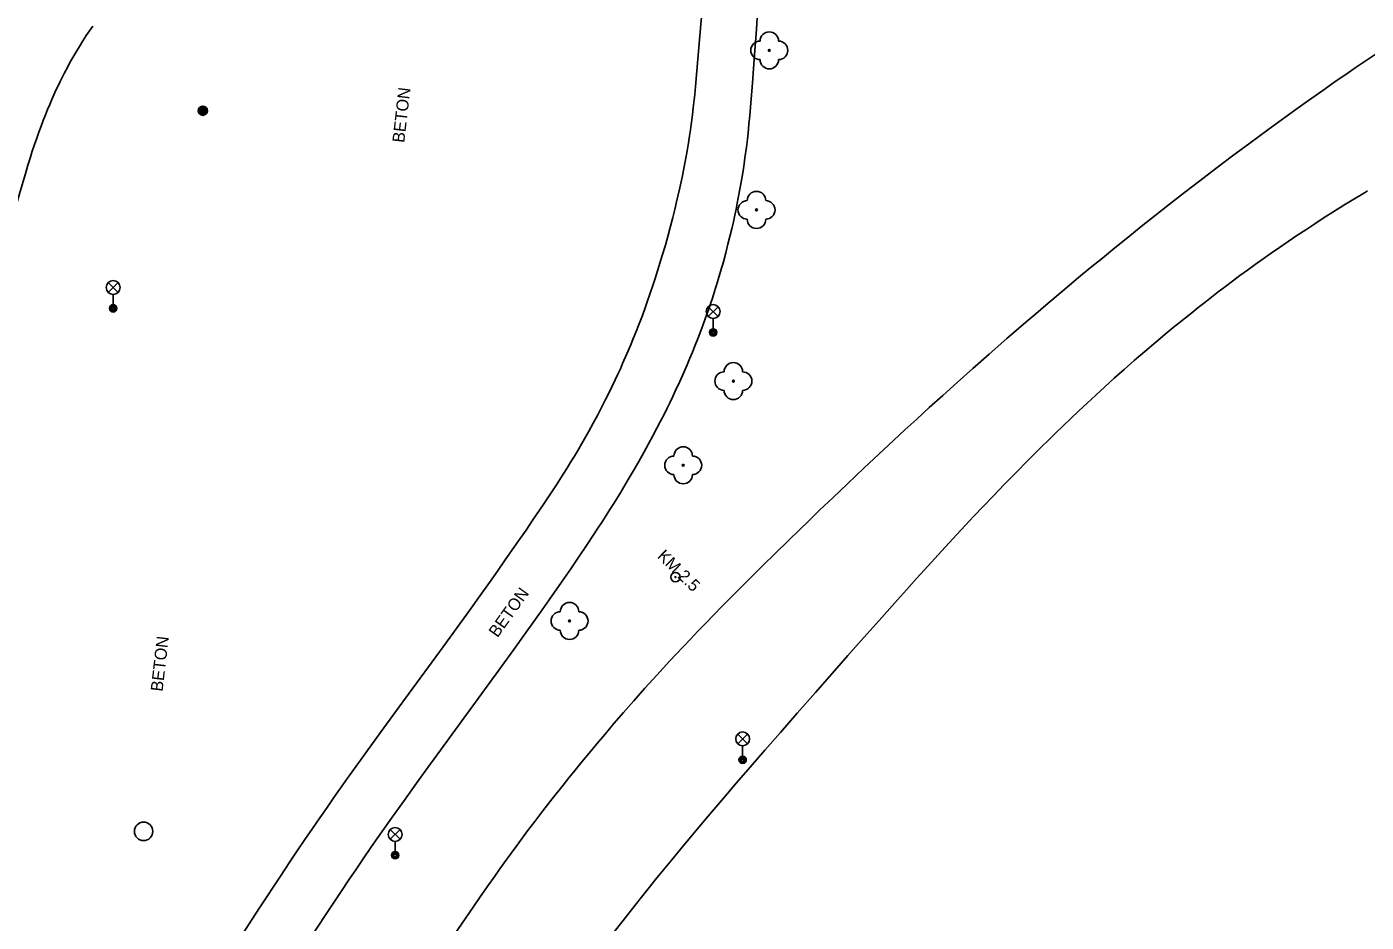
# Model space of a CAD drawing. Extents: x -541281 to -539153, y -1183881 to -1182141.
# Drawn here: x -539853.2 to -539780.8, y -1183251.4 to -1183203.1 of the extents above; entities that cross this region are included whole.
import ezdxf

# ---------------------------------------------------------------- set-up
doc = ezdxf.new("R2010")
doc.units = 0
for name, color, linetype in [('Vrstva 10', 7, 'Continuous'), ('Vrstva 11', 7, 'Continuous'), ('Vrstva 13', 7, 'Continuous'), ('Vrstva 22', 7, 'Continuous'), ('Vrstva 25', 7, 'Continuous'), ('Vrstva 27', 7, 'Continuous'), ('Vrstva 33', 7, 'Continuous'), ('Vrstva 40', 7, 'Continuous')]:
    doc.layers.add(name, color=color, linetype=linetype)

msp = doc.modelspace()

# ---------------------------------------------------------------- linework, layer by layer
at = {"layer": 'Vrstva 10'}
for p, q in [((-539792.209, -1183220.104), (-539792.806, -1183220.612)), ((-539799.777, -1183227.166), (-539800.402, -1183227.806)), ((-539814.125, -1183243.071), (-539814.863, -1183243.926)), ((-539820.984, -1183251.348), (-539821.54, -1183252.067))]:
    msp.add_line(p, q, dxfattribs=at)
for points in [[(-539850.169, -1183203.826), (-539849.984, -1183203.542), (-539849.806, -1183203.278), (-539849.635, -1183203.033)], [(-539852.902, -1183209.788), (-539852.783, -1183209.431), (-539852.664, -1183209.086), (-539852.546, -1183208.755), (-539852.428, -1183208.435), (-539852.311, -1183208.126), (-539852.194, -1183207.829), (-539852.078, -1183207.542), (-539851.963, -1183207.266), (-539851.848, -1183207), (-539851.735, -1183206.744), (-539851.622, -1183206.496), (-539851.51, -1183206.258), (-539851.4, -1183206.028), (-539851.291, -1183205.807), (-539851.182, -1183205.594), (-539851.076, -1183205.388), (-539850.97, -1183205.19), (-539850.866, -1183204.999), (-539850.763, -1183204.815), (-539850.559, -1183204.46), (-539850.361, -1183204.131), (-539850.169, -1183203.826)], [(-539853.14, -1183210.542), (-539853.021, -1183210.158), (-539852.902, -1183209.788)], [(-539855.674, -1183219.912), (-539855.544, -1183219.349), (-539855.419, -1183218.822), (-539855.298, -1183218.328), (-539855.184, -1183217.865), (-539854.962, -1183216.999), (-539854.763, -1183216.241), (-539854.585, -1183215.579), (-539854.426, -1183214.999), (-539854.143, -1183213.985), (-539853.926, -1183213.224), (-539853.596, -1183212.083), (-539853.26, -1183210.94), (-539853.14, -1183210.542)], [(-539780.767, -1183211.929), (-539780.94, -1183212.03), (-539781.504, -1183212.371), (-539782.052, -1183212.709), (-539782.587, -1183213.044), (-539783.108, -1183213.376), (-539783.616, -1183213.704), (-539784.111, -1183214.029), (-539784.594, -1183214.351)], [(-539784.594, -1183214.351), (-539785.065, -1183214.67), (-539785.525, -1183214.985), (-539785.974, -1183215.297), (-539786.411, -1183215.606), (-539786.839, -1183215.912), (-539787.256, -1183216.214), (-539787.664, -1183216.513), (-539788.062, -1183216.808), (-539788.451, -1183217.1), (-539788.832, -1183217.389), (-539789.203, -1183217.675), (-539789.567, -1183217.958), (-539789.922, -1183218.237), (-539790.27, -1183218.513), (-539790.61, -1183218.785), (-539790.943, -1183219.054), (-539791.268, -1183219.321), (-539791.587, -1183219.584), (-539792.209, -1183220.104)], [(-539792.806, -1183220.612), (-539793.378, -1183221.106), (-539793.927, -1183221.589), (-539794.455, -1183222.059), (-539794.961, -1183222.517), (-539795.449, -1183222.963), (-539795.917, -1183223.397), (-539796.368, -1183223.82), (-539796.802, -1183224.232), (-539797.22, -1183224.632), (-539797.623, -1183225.022), (-539798.011, -1183225.401), (-539798.386, -1183225.77), (-539799.107, -1183226.488), (-539799.777, -1183227.166)], [(-539800.402, -1183227.806), (-539800.984, -1183228.41), (-539801.527, -1183228.979)], [(-539801.527, -1183228.979), (-539802.035, -1183229.515), (-539802.509, -1183230.02), (-539802.952, -1183230.496), (-539803.781, -1183231.393), (-539804.503, -1183232.184), (-539805.134, -1183232.88), (-539805.686, -1183233.492), (-539806.169, -1183234.031), (-539807.014, -1183234.978), (-539807.648, -1183235.693), (-539808.125, -1183236.232)], [(-539808.125, -1183236.232), (-539808.841, -1183237.043), (-539809.56, -1183237.86), (-539810.602, -1183239.045), (-539811.576, -1183240.152), (-539812.485, -1183241.189), (-539813.333, -1183242.16), (-539814.125, -1183243.071)], [(-539814.863, -1183243.926), (-539815.552, -1183244.728), (-539816.194, -1183245.482), (-539816.793, -1183246.191), (-539817.352, -1183246.857), (-539817.873, -1183247.483), (-539818.359, -1183248.072), (-539818.813, -1183248.626), (-539819.236, -1183249.147), (-539819.631, -1183249.637), (-539819.999, -1183250.098), (-539820.343, -1183250.532), (-539820.984, -1183251.348)]]:
    msp.add_lwpolyline(points, dxfattribs=at)
at = {"layer": 'Vrstva 11'}
for p, q in [((-539814.186, -1183208.336), (-539814.14, -1183207.85)), ((-539816.269, -1183218.037), (-539816.165, -1183217.724)), ((-539821.575, -1183222.48), (-539821.416, -1183222.148)), ((-539826.312, -1183235.908), (-539825.807, -1183235.198)), ((-539839.46, -1183248.9), (-539839.021, -1183248.235))]:
    msp.add_line(p, q, dxfattribs=at)
for points in [[(-539816.878, -1183203.973), (-539816.58, -1183200.482), (-539816.434, -1183198.736), (-539816.29, -1183196.99), (-539816.22, -1183196.185), (-539816.164, -1183195.582), (-539816.124, -1183195.129), (-539816.096, -1183194.79), (-539816.059, -1183194.28), (-539816.043, -1183194.025)], [(-539814.14, -1183207.85), (-539814.062, -1183206.953), (-539813.994, -1183206.113), (-539813.934, -1183205.324), (-539813.881, -1183204.585), (-539813.786, -1183203.198), (-539813.629, -1183200.771), (-539813.508, -1183198.951)], [(-539818.193, -1183212.933), (-539818.094, -1183212.522), (-539818.005, -1183212.137), (-539817.925, -1183211.776), (-539817.852, -1183211.437), (-539817.786, -1183211.118), (-539817.726, -1183210.82), (-539817.619, -1183210.259), (-539817.531, -1183209.767), (-539817.459, -1183209.336), (-539817.4, -1183208.958), (-539817.35, -1183208.628), (-539817.309, -1183208.338), (-539817.243, -1183207.83), (-539817.197, -1183207.448), (-539817.164, -1183207.162), (-539817.12, -1183206.731), (-539817.08, -1183206.3), (-539816.878, -1183203.973)], [(-539816.165, -1183217.724), (-539816.066, -1183217.421), (-539815.973, -1183217.126), (-539815.884, -1183216.841), (-539815.719, -1183216.287), (-539815.571, -1183215.767), (-539815.439, -1183215.279), (-539815.32, -1183214.82), (-539815.213, -1183214.389), (-539815.117, -1183213.985), (-539815.031, -1183213.605), (-539814.953, -1183213.249), (-539814.883, -1183212.915), (-539814.82, -1183212.601), (-539814.763, -1183212.306), (-539814.661, -1183211.753), (-539814.577, -1183211.268), (-539814.508, -1183210.843), (-539814.452, -1183210.471), (-539814.405, -1183210.145), (-539814.328, -1183209.573), (-539814.275, -1183209.143), (-539814.238, -1183208.82), (-539814.186, -1183208.336)], [(-539821.416, -1183222.148), (-539821.27, -1183221.835), (-539821.135, -1183221.54), (-539821.011, -1183221.263), (-539820.782, -1183220.741), (-539820.587, -1183220.282), (-539820.42, -1183219.877), (-539820.277, -1183219.522), (-539820.155, -1183219.21), (-539819.946, -1183218.66), (-539819.794, -1183218.246), (-539819.682, -1183217.934), (-539819.518, -1183217.463), (-539819.36, -1183216.99), (-539819.253, -1183216.661), (-539819.051, -1183216.022), (-539818.869, -1183215.423), (-539818.705, -1183214.86), (-539818.557, -1183214.331), (-539818.423, -1183213.835), (-539818.302, -1183213.37), (-539818.193, -1183212.933)], [(-539820.436, -1183227.071), (-539820.137, -1183226.552), (-539819.862, -1183226.063), (-539819.609, -1183225.601), (-539819.375, -1183225.167), (-539819.159, -1183224.758), (-539818.961, -1183224.373), (-539818.777, -1183224.01), (-539818.607, -1183223.668), (-539818.451, -1183223.347), (-539818.306, -1183223.044), (-539818.172, -1183222.76), (-539817.925, -1183222.223), (-539817.714, -1183221.751), (-539817.534, -1183221.335), (-539817.379, -1183220.97), (-539817.246, -1183220.649), (-539817.131, -1183220.366), (-539816.935, -1183219.87), (-539816.792, -1183219.495), (-539816.686, -1183219.213), (-539816.531, -1183218.788), (-539816.38, -1183218.36), (-539816.269, -1183218.037)], [(-539822.136, -1183223.606), (-539821.933, -1183223.208), (-539821.747, -1183222.833), (-539821.575, -1183222.48)], [(-539827.387, -1183231.93), (-539826.721, -1183230.976), (-539826.225, -1183230.257), (-539825.856, -1183229.715), (-539825.305, -1183228.9), (-539824.76, -1183228.08), (-539824.548, -1183227.756), (-539824.345, -1183227.44), (-539824.151, -1183227.134), (-539823.965, -1183226.835), (-539823.787, -1183226.545), (-539823.616, -1183226.263), (-539823.453, -1183225.989), (-539823.143, -1183225.455), (-539822.858, -1183224.952), (-539822.597, -1183224.476), (-539822.357, -1183224.028), (-539822.136, -1183223.606)], [(-539825.807, -1183235.198), (-539825.366, -1183234.576), (-539824.982, -1183234.03), (-539824.314, -1183233.071), (-539823.817, -1183232.349), (-539823.447, -1183231.805), (-539822.896, -1183230.985), (-539822.35, -1183230.16), (-539822.123, -1183229.812), (-539821.905, -1183229.474), (-539821.696, -1183229.146), (-539821.496, -1183228.827), (-539821.113, -1183228.207), (-539820.76, -1183227.622), (-539820.436, -1183227.071)], [(-539828.209, -1183233.092), (-539827.77, -1183232.473), (-539827.387, -1183231.93)], [(-539833.907, -1183240.938), (-539832.748, -1183239.348), (-539830.715, -1183236.566), (-539829.954, -1183235.52), (-539829.291, -1183234.603), (-539828.713, -1183233.798), (-539828.209, -1183233.092)], [(-539827.559, -1183237.637), (-539826.893, -1183236.716), (-539826.312, -1183235.908)], [(-539832.801, -1183244.847), (-539832.145, -1183243.934), (-539831.527, -1183243.08), (-539830.364, -1183241.482), (-539828.323, -1183238.687), (-539827.559, -1183237.637)], [(-539839.021, -1183248.235), (-539838.593, -1183247.594), (-539838.175, -1183246.976), (-539837.767, -1183246.378), (-539837.37, -1183245.802), (-539836.982, -1183245.245), (-539836.605, -1183244.706), (-539835.87, -1183243.667), (-539835.176, -1183242.695), (-539834.522, -1183241.787), (-539833.907, -1183240.938)], [(-539834.233, -1183246.872), (-539833.497, -1183245.825), (-539832.801, -1183244.847)], [(-539839.117, -1183254.196), (-539837.886, -1183252.313), (-539836.65, -1183250.43), (-539836.222, -1183249.783), (-539835.804, -1183249.159), (-539835.396, -1183248.557), (-539834.998, -1183247.975), (-539834.611, -1183247.414), (-539834.233, -1183246.872)], [(-539844.807, -1183257.195), (-539844.147, -1183256.153), (-539843.568, -1183255.242), (-539842.549, -1183253.652), (-539841.781, -1183252.461), (-539840.623, -1183250.679), (-539839.46, -1183248.9)]]:
    msp.add_lwpolyline(points, dxfattribs=at)
at = {"layer": 'Vrstva 13'}
msp.add_line((-539802.936, -1183222.28), (-539803.716, -1183222.981), dxfattribs=at)
for points in [[(-539778.983, -1183203.634), (-539779.599, -1183204.044), (-539780.204, -1183204.45), (-539780.797, -1183204.851), (-539781.38, -1183205.248), (-539781.951, -1183205.641), (-539782.512, -1183206.03), (-539783.062, -1183206.414), (-539783.602, -1183206.794), (-539784.132, -1183207.17), (-539784.653, -1183207.542), (-539785.164, -1183207.91), (-539786.166, -1183208.638), (-539787.132, -1183209.349)], [(-539787.132, -1183209.349), (-539788.063, -1183210.043), (-539788.961, -1183210.72), (-539789.827, -1183211.381), (-539790.663, -1183212.025), (-539791.469, -1183212.654), (-539792.246, -1183213.266), (-539792.997, -1183213.863), (-539793.722, -1183214.444), (-539794.422, -1183215.01)], [(-539794.422, -1183215.01), (-539795.097, -1183215.561), (-539795.75, -1183216.098)], [(-539795.75, -1183216.098), (-539796.38, -1183216.62), (-539796.989, -1183217.128), (-539797.577, -1183217.622), (-539798.145, -1183218.103), (-539798.695, -1183218.571), (-539799.226, -1183219.026), (-539800.25, -1183219.912), (-539801.207, -1183220.748), (-539802.101, -1183221.536), (-539802.936, -1183222.28)], [(-539803.716, -1183222.981), (-539804.445, -1183223.641), (-539805.126, -1183224.263), (-539805.764, -1183224.848), (-539806.36, -1183225.399)], [(-539806.36, -1183225.399), (-539806.918, -1183225.918), (-539807.961, -1183226.895), (-539808.87, -1183227.754), (-539809.663, -1183228.51), (-539810.355, -1183229.175), (-539810.96, -1183229.758), (-539812.015, -1183230.785), (-539812.804, -1183231.558), (-539813.394, -1183232.141)], [(-539813.394, -1183232.141), (-539814.278, -1183233.018), (-539815.16, -1183233.9), (-539815.632, -1183234.376), (-539816.086, -1183234.838), (-539816.522, -1183235.287), (-539816.943, -1183235.723), (-539817.348, -1183236.148), (-539817.738, -1183236.56), (-539818.113, -1183236.96), (-539818.475, -1183237.349), (-539818.823, -1183237.727), (-539819.159, -1183238.094), (-539819.805, -1183238.809)], [(-539819.805, -1183238.809), (-539820.405, -1183239.483), (-539820.962, -1183240.118)], [(-539820.962, -1183240.118), (-539821.479, -1183240.717), (-539821.961, -1183241.281), (-539822.409, -1183241.813), (-539822.826, -1183242.313), (-539823.214, -1183242.785), (-539823.576, -1183243.229), (-539823.913, -1183243.647), (-539824.228, -1183244.04), (-539824.813, -1183244.782), (-539825.32, -1183245.436), (-539825.76, -1183246.012), (-539826.143, -1183246.518), (-539826.475, -1183246.963), (-539826.765, -1183247.354)], [(-539826.765, -1183247.354), (-539827.268, -1183248.043), (-539827.642, -1183248.563)], [(-539827.642, -1183248.563), (-539827.921, -1183248.955), (-539828.337, -1183249.545), (-539828.75, -1183250.14), (-539829.327, -1183250.98), (-539829.881, -1183251.795), (-539830.414, -1183252.585), (-539830.927, -1183253.352), (-539831.42, -1183254.096), (-539831.895, -1183254.818), (-539832.352, -1183255.518), (-539832.791, -1183256.198), (-539833.215, -1183256.857)]]:
    msp.add_lwpolyline(points, dxfattribs=at)
at = {"layer": 'Vrstva 22'}
for centre in [(-539813.09, -1183204.34), (-539813.78, -1183212.96), (-539815.03, -1183222.21), (-539817.74, -1183226.76), (-539823.88, -1183235.17)]:
    msp.add_circle(centre, 0.05, dxfattribs=at)
for centre, start, end in [((-539813.09, -1183203.84), 359.99973, 179.99973), ((-539813.59, -1183204.34), 89.99973, 269.99973), ((-539812.59, -1183204.34), 269.99973, 89.99973), ((-539813.09, -1183204.84), 179.99973, 359.99973), ((-539813.78, -1183212.46), 359.99973, 179.99973), ((-539814.28, -1183212.96), 89.99973, 269.99973), ((-539813.28, -1183212.96), 269.99973, 89.99973), ((-539813.78, -1183213.46), 179.99973, 359.99973), ((-539815.03, -1183221.71), 359.99973, 179.99973), ((-539815.53, -1183222.21), 89.99973, 269.99973), ((-539814.53, -1183222.21), 269.99973, 89.99973), ((-539815.03, -1183222.71), 179.99973, 359.99973), ((-539817.74, -1183226.26), 359.99973, 179.99973), ((-539818.24, -1183226.76), 89.99973, 269.99973), ((-539817.24, -1183226.76), 269.99973, 89.99973), ((-539817.74, -1183227.26), 179.99973, 359.99973), ((-539823.88, -1183234.67), 360, 180), ((-539824.38, -1183235.17), 90, 270), ((-539823.38, -1183235.17), 270, 90), ((-539823.88, -1183235.67), 179.99999, 359.99999)]:
    msp.add_arc(centre, 0.5, start, end, dxfattribs=at)
at = {"layer": 'Vrstva 25'}
for centre, radius in [((-539843.69, -1183207.6), 0.25), ((-539843.69, -1183207.6), 0.2), ((-539843.69, -1183207.6), 0.15), ((-539843.69, -1183207.6), 0.1), ((-539843.69, -1183207.6), 0.05), ((-539818.16, -1183232.8), 0.25), ((-539818.16, -1183232.8), 0.0303)]:
    msp.add_circle(centre, radius, dxfattribs=at)
at = {"layer": 'Vrstva 27'}
msp.add_circle((-539846.89, -1183246.54), 0.5, dxfattribs=at)
at = {"layer": 'Vrstva 33'}
for p, q in [((-539848.795, -1183217.42), (-539848.265, -1183216.89)), ((-539848.795, -1183216.89), (-539848.265, -1183217.42)), ((-539848.53, -1183217.53), (-539848.53, -1183218.28)), ((-539816.385, -1183218.72), (-539815.855, -1183218.19)), ((-539816.385, -1183218.19), (-539815.855, -1183218.72)), ((-539816.12, -1183218.83), (-539816.12, -1183219.58)), ((-539814.795, -1183241.81), (-539814.265, -1183241.28)), ((-539814.795, -1183241.28), (-539814.265, -1183241.81)), ((-539814.53, -1183241.92), (-539814.53, -1183242.67)), ((-539833.565, -1183246.97), (-539833.035, -1183246.44)), ((-539833.565, -1183246.44), (-539833.035, -1183246.97)), ((-539833.3, -1183247.08), (-539833.3, -1183247.83))]:
    msp.add_line(p, q, dxfattribs=at)
for centre, radius in [((-539848.53, -1183217.155), 0.375), ((-539848.53, -1183218.28), 0.2), ((-539848.53, -1183218.28), 0.145), ((-539848.53, -1183218.28), 0.0876), ((-539816.12, -1183218.455), 0.375), ((-539816.12, -1183219.58), 0.2), ((-539816.12, -1183219.58), 0.145), ((-539816.12, -1183219.58), 0.0876), ((-539814.53, -1183241.545), 0.375), ((-539814.53, -1183242.67), 0.2), ((-539814.53, -1183242.67), 0.145), ((-539814.53, -1183242.67), 0.0876), ((-539833.3, -1183246.705), 0.375), ((-539833.3, -1183247.83), 0.2), ((-539833.3, -1183247.83), 0.145), ((-539833.3, -1183247.83), 0.0876)]:
    msp.add_circle(centre, radius, dxfattribs=at)

# ---------------------------------------------------------------- texts
at = {"layer": 'Vrstva 40'}
for s, rotation, p in [('BETON', 83.4475, (-539832.811, -1183209.354)), ('KM 2.5', 315.55302, (-539819.181, -1183231.715)), ('BETON', 54.53062, (-539827.771, -1183236.107)), ('BETON', 83.4475, (-539845.867, -1183239.007))]:
    msp.add_text(s, height=0.65, rotation=rotation, dxfattribs=at).set_placement(p)

doc.saveas('drawing.dxf')
